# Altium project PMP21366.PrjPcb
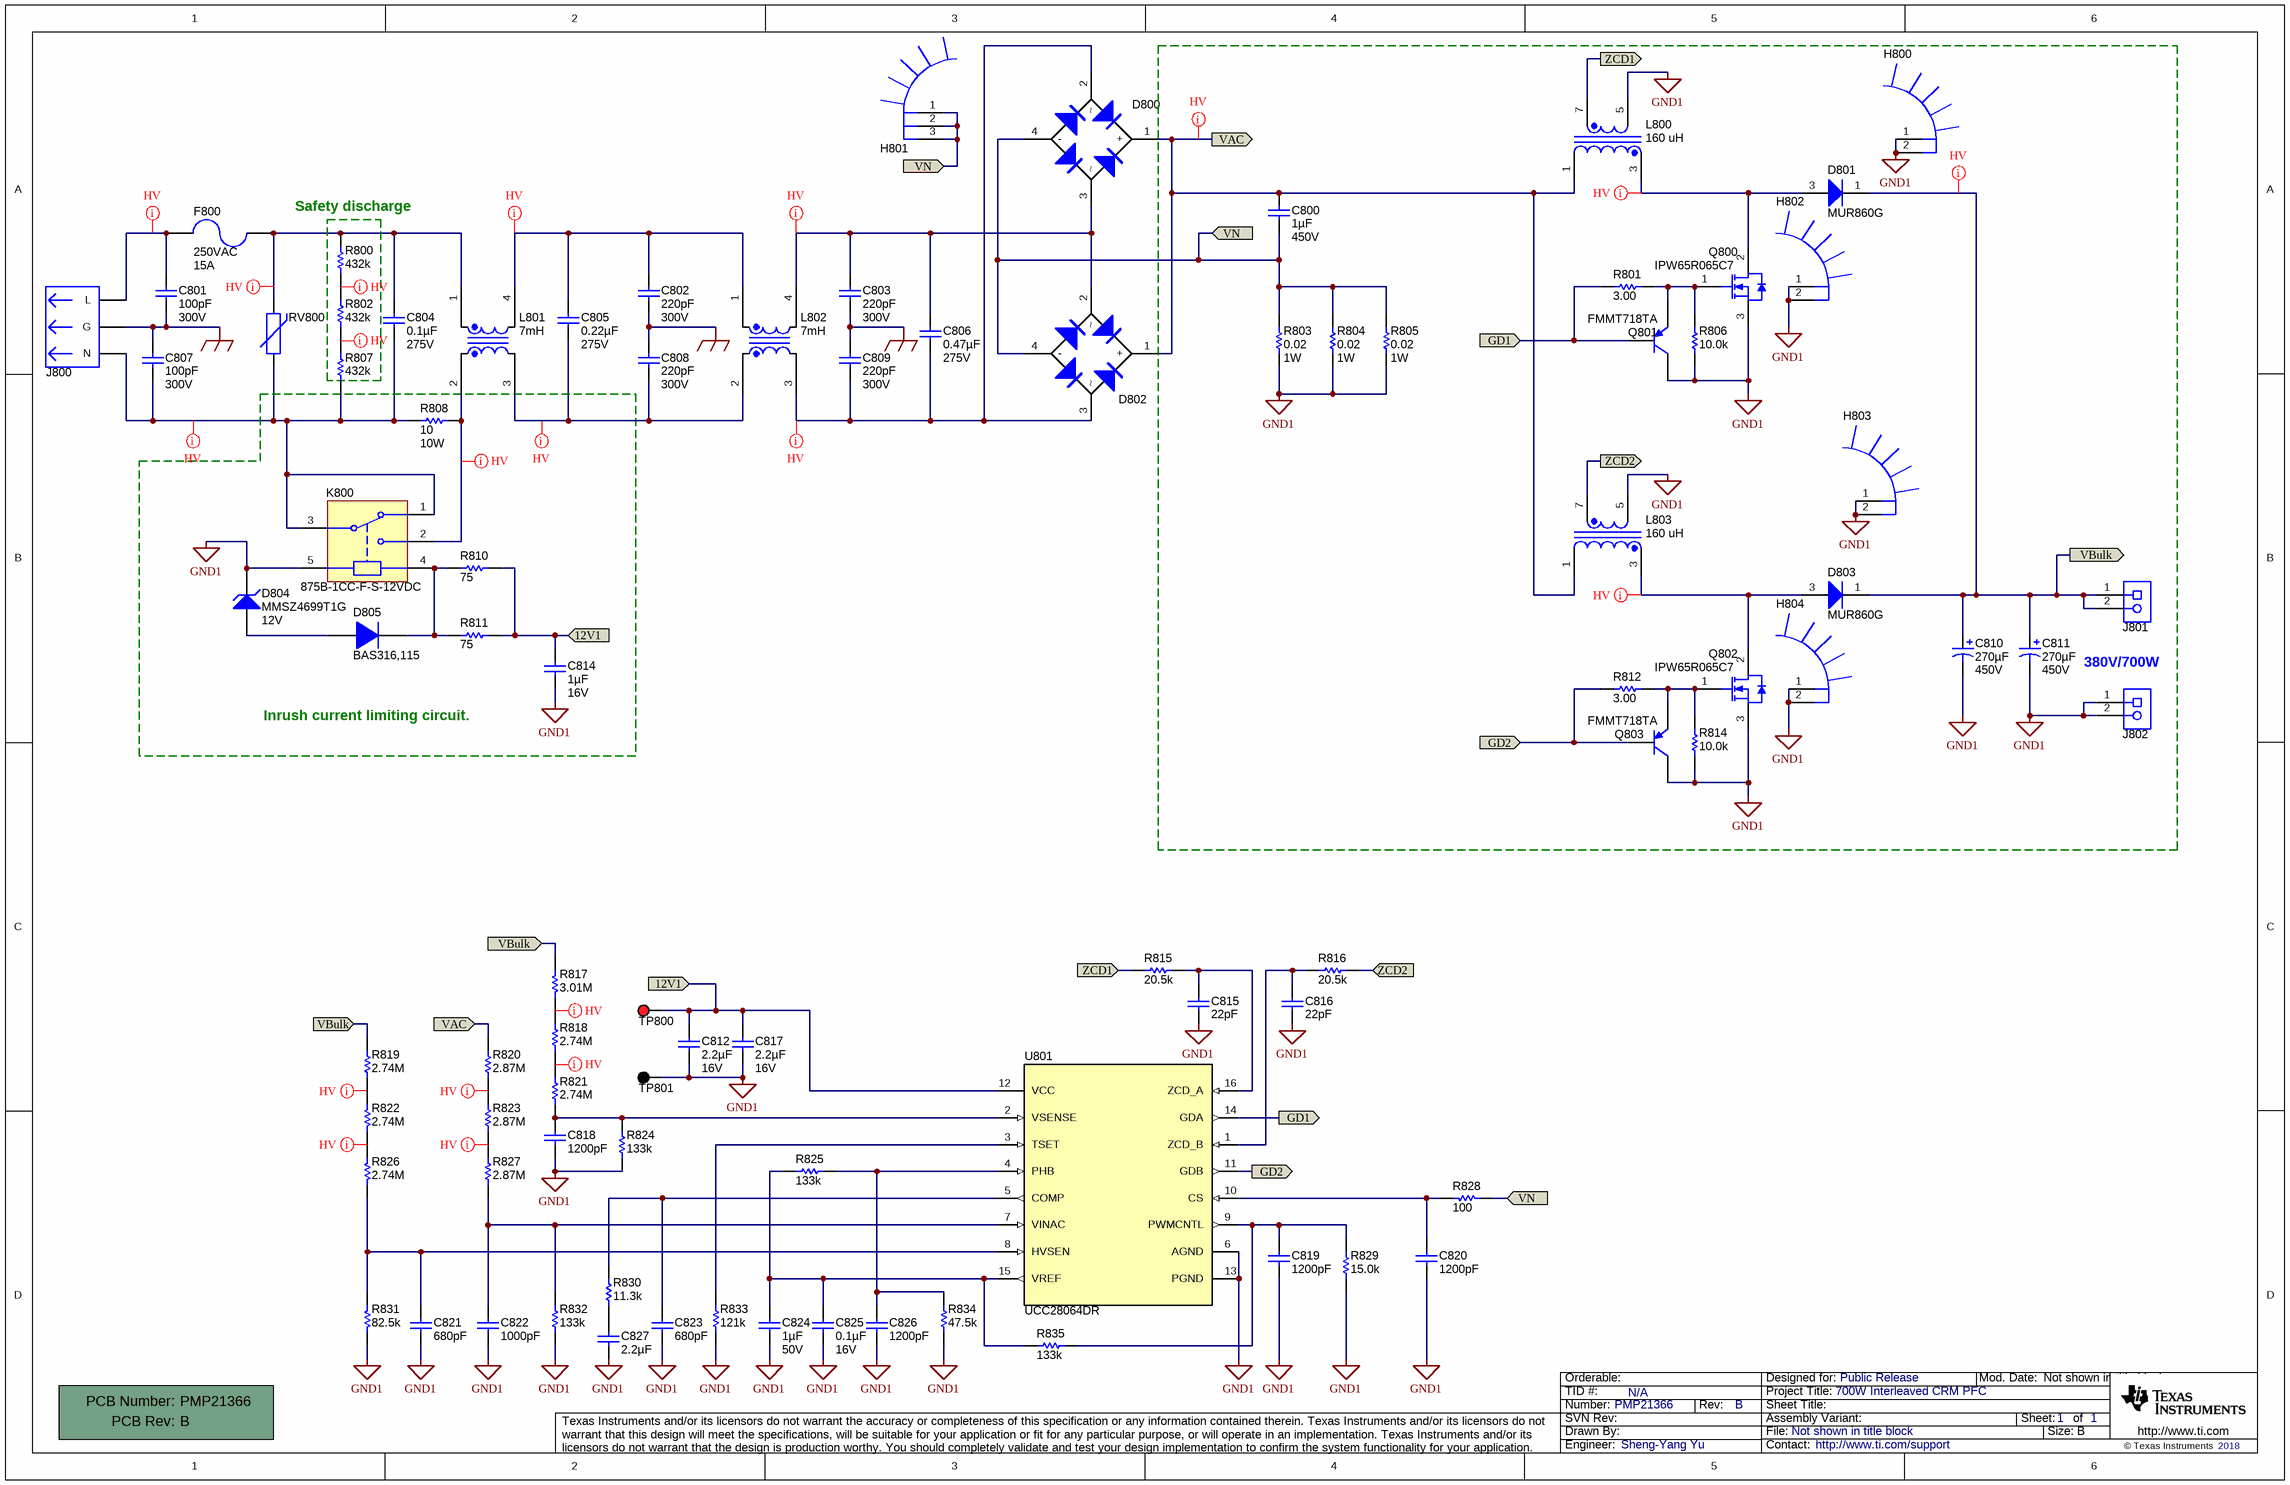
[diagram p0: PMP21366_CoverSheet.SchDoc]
TID: N/A; TechSupport: http://www.ti.com/support; SCH_Rev: B; PRJ_Title: 700W Interleaved CRM PFC; PRJ_Number: PMP21366; PRJ_Engineer: Sheng-Yang Yu; PRJ_Customer: Public Release; PCB_Rev: B; PCB_Layout: Sheng-Yang Yu; CopyrightYear: 2018
1 sheet, 90 parts. Net scope: flat (ports and power ports of the same name join across sheets).
Board file: PMP21366_PCB.PcbDoc

## Sheet PMP21366_CoverSheet.SchDoc
size 431 x 279 mm; Date: Not shown in title block; ApprovedBy: Not shown in title block; CheckedBy: Not shown in title block; Author: Not shown in title block; CompanyName: Not shown in title block; Engineer: Not shown in title block; Organization: Not shown in title block; Address1: Not shown in title block; Address2: Not shown in title block; Address3: Not shown in title block; Address4: Not shown in title block; DocumentNumber: 1; Revision: Use project parameter SCH_Rev; SheetNumber: 1; SheetTotal: 1; PageSetup: Record=PageOptions¦CenterHorizontal=True¦CenterVertical=True¦PrintScale=1.00¦XCorrection=1.00¦YCorrection=1.00¦PrintKind=0¦BorderSize=5000000¦LeftOffset=0¦BottomOffset=0¦Orientation=2¦PaperLength=1000¦PaperWidth=1000¦Scale=100¦PaperSource=15¦PrintQuality=600¦MediaType=1¦DitherType=10¦PaperKind=Letter¦PrintScaleMode=1

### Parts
!PCB800  Printed Circuit Board  (value not drawn)  (mechanical)
C800  ValueDisplayed: 1µF  Value2: 450V  [MPK_1800x950]  (hidden comment: 450MPK105J)
C801  ValueDisplayed: 100pF  VAC_Y: 300V  [KY_700x500x1000]  (hidden comment: DE2B3KY101KN3AU02F)
C802  ValueDisplayed: 220pF  Value2: 300V  [VY2_750x500]  (hidden comment: DE2B3KY221KA3BU02F)
C803  ValueDisplayed: 220pF  Value2: 300V  [VY2_750x500]  (hidden comment: DE2B3KY221KA3BU02F)
C804  ValueDisplayed: 0.1µF  VAC_X: 275V  [WCAP-FTX2_1800x600x1200]  (hidden comment: 890324025017)
C805  ValueDisplayed: 0.22µF  Value2: 275V  [CAPRR1500W60L1750T800H1650]  (hidden comment: ECQ-U2A224ML)
C806  ValueDisplayed: 0.47µF  VAC_X: 275V  [WCAP-FTX2_1500x1000x1600]  (hidden comment: 890324024005)
C807  ValueDisplayed: 100pF  VAC_Y: 300V  [KY_700x500x1000]  (hidden comment: DE2B3KY101KN3AU02F)
C808  ValueDisplayed: 220pF  Value2: 300V  [VY2_750x500]  (hidden comment: DE2B3KY221KA3BU02F)
C809  ValueDisplayed: 220pF  Value2: 300V  [VY2_750x500]  (hidden comment: DE2B3KY221KA3BU02F)
C810  ValueDisplayed: 270µF  Value2: 450V  [380LQ_3000x3000]  (hidden comment: 450VXH270MEFCSN30X30)
C811  ValueDisplayed: 270µF  Value2: 450V  [380LQ_3000x3000]  (hidden comment: 450VXH270MEFCSN30X30)
C812  ValueDisplayed: 2.2µF  Value2: 16V  [0805_HV]  (hidden comment: 0805YD225KAT2A)
C814  ValueDisplayed: 1µF  Value2: 16V  [0805_HV]  (hidden comment: 0805YD105KAT2A)
C815  ValueDisplayed: 22pF  [0603]  (hidden comment: C0603C220J5GACTU)
C816  ValueDisplayed: 22pF  [0603]  (hidden comment: C0603C220J5GACTU)
C817  ValueDisplayed: 2.2µF  Value2: 16V  [0805_HV]  (hidden comment: 0805YD225KAT2A)
C818  ValueDisplayed: 1200pF  [0603]  (hidden comment: 06031C122JAT2A)
C819  ValueDisplayed: 1200pF  [0603]  (hidden comment: 06031C122JAT2A)
C820  ValueDisplayed: 1200pF  [0603]  (hidden comment: 06031C122JAT2A)
C821  ValueDisplayed: 680pF  [0603]  (hidden comment: GRM188R71H681KA01D)
C822  ValueDisplayed: 1000pF  [0603]  (hidden comment: 06031C102MAT2A)
C823  ValueDisplayed: 680pF  [0603]  (hidden comment: GRM188R71H681KA01D)
C824  ValueDisplayed: 1µF  Value2: 50V  [0603]  (hidden comment: UMK107AB7105KA-T)
C825  ValueDisplayed: 0.1µF  Value2: 16V  [0603]  (hidden comment: EMK107B7104KA-T)
C826  ValueDisplayed: 1200pF  [0603]  (hidden comment: 06031C122JAT2A)
C827  ValueDisplayed: 2.2µF  [0805_HV]  (hidden comment: 0805YD225KAT2A)
D800  D25XB60-7000  [5S]  (value not drawn)
D801  MUR860G  [TO-220AC]
D802  D25XB60-7000  [5S]  (value not drawn)
D803  MUR860G  [TO-220AC]
D804  MMSZ4699T1G  value 12V  [SOD-123]
D805  BAS316,115  [sod-323]
F800  VDC_V: 250VAC  Irating_A: 15A  [Fuse_217_015]  (hidden comment: 0217015.MXEP)
H800  513002B02500G  [HSINK_513201B02500]  (value not drawn)
H801  782653B04250G  [HEATSINK_782653B04250G]  (value not drawn)
H802  513002B02500G  [HSINK_513201B02500]  (value not drawn)
H803  513002B02500G  [HSINK_513201B02500]  (value not drawn)
H804  513002B02500G  [HSINK_513201B02500]  (value not drawn)
J800  703W-00/54  [CONN_QUALTEK-703W-0054]  (value not drawn)
J801  1715721  [PhoenixContact_1715721]  (value not drawn)
J802  1715721  [PhoenixContact_1715721]  (value not drawn)
K800  875B-1CC-F-S-12VDC  [RELAY_875]
L800  value 160 uH  [TDK_PFC4124QM-161K06D-00]  (hidden comment: PFC4124QM-161K06D-00)
L801  ValueDisplayed: 7mH  [WE-CMBNC_L]  (hidden comment: 7448040707)
L802  ValueDisplayed: 7mH  [WE-CMBNC_L]  (hidden comment: 7448040707)
L803  value 160 uH  [TDK_PFC4124QM-161K06D-00]  (hidden comment: PFC4124QM-161K06D-00)
Q800  IPW65R065C7  [TO-247]
Q801  FMMT718TA  [SOT-23]
Q802  IPW65R065C7  [TO-247]
Q803  FMMT718TA  [SOT-23]
R800  ValueDisplayed: 432k  [1206]  (hidden comment: CRCW1206432KFKEA)
R801  ValueDisplayed: 3.00  [1206]  (hidden comment: RC1206FR-073RL)
R802  ValueDisplayed: 432k  [1206]  (hidden comment: CRCW1206432KFKEA)
R803  ValueDisplayed: 0.02  Value2: 1W  [2010]  (hidden comment: CSRN2010FK20L0)
R804  ValueDisplayed: 0.02  Value2: 1W  [2010]  (hidden comment: CSRN2010FK20L0)
R805  ValueDisplayed: 0.02  Value2: 1W  [2010]  (hidden comment: CSRN2010FK20L0)
R806  ValueDisplayed: 10.0k  [0805_HV]  (hidden comment: CRCW080510K0FKEA)
R807  ValueDisplayed: 432k  [1206]  (hidden comment: CRCW1206432KFKEA)
R808  ValueDisplayed: 10  Value2: 10W  [TWW10]  (hidden comment: TWW10J10RE)
R810  ValueDisplayed: 75  [1206]  (hidden comment: CRCW120675R0JNEA)
R811  ValueDisplayed: 75  [1206]  (hidden comment: CRCW120675R0JNEA)
R812  ValueDisplayed: 3.00  [1206]  (hidden comment: RC1206FR-073RL)
R814  ValueDisplayed: 10.0k  [0805_HV]  (hidden comment: CRCW080510K0FKEA)
R815  ValueDisplayed: 20.5k  [0603]  (hidden comment: CRCW060320K5FKEA)
R816  ValueDisplayed: 20.5k  [0603]  (hidden comment: CRCW060320K5FKEA)
R817  ValueDisplayed: 3.01M  [0805_HV]  (hidden comment: CRCW08053M01FKEA)
R818  ValueDisplayed: 2.74M  [0805_HV]  (hidden comment: CRCW08052M74FKEA)
R819  ValueDisplayed: 2.74M  [0805_HV]  (hidden comment: CRCW08052M74FKEA)
R820  ValueDisplayed: 2.87M  [0805_HV]  (hidden comment: CRCW08052M87FKEA)
R821  ValueDisplayed: 2.74M  [0805_HV]  (hidden comment: CRCW08052M74FKEA)
R822  ValueDisplayed: 2.74M  [0805_HV]  (hidden comment: CRCW08052M74FKEA)
R823  ValueDisplayed: 2.87M  [0805_HV]  (hidden comment: CRCW08052M87FKEA)
R824  ValueDisplayed: 133k  [0603]  (hidden comment: CRCW0603133KFKEA)
R825  ValueDisplayed: 133k  [0603]  (hidden comment: CRCW0603133KFKEA)
R826  ValueDisplayed: 2.74M  [0805_HV]  (hidden comment: CRCW08052M74FKEA)
R827  ValueDisplayed: 2.87M  [0805_HV]  (hidden comment: CRCW08052M87FKEA)
R828  ValueDisplayed: 100  [0603]  (hidden comment: CRCW0603100RFKEA)
R829  ValueDisplayed: 15.0k  [0603]  (hidden comment: CRCW060315K0FKEA)
R830  ValueDisplayed: 11.3k  [0603]  (hidden comment: CRCW060311K3FKEA)
R831  ValueDisplayed: 82.5k  [0603]  (hidden comment: CRCW060382K5FKEA)
R832  ValueDisplayed: 133k  [0603]  (hidden comment: CRCW0603133KFKEA)
R833  ValueDisplayed: 121k  [0603]  (hidden comment: CRCW0603121KFKEA)
R834  ValueDisplayed: 47.5k  [0603]  (hidden comment: RC0603FR-0747K5L)
R835  ValueDisplayed: 133k  [0603]  (hidden comment: CRCW0603133KFKEA)
RV800  S10K275E2  [VAR_S10K275E2]  (value not drawn)
TP800  5000  [Keystone5000]  (value not drawn)
TP801  5001  [Keystone5001]  (value not drawn)
U801  UCC28064DR  [D0016A_N]

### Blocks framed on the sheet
380V/700W: C800 C810 C811 D801 D803 H800 H802-H804 J801 J802 L800 L803 Q800-Q803 R801 R803-R806 R812 R814
Safety discharge: R800 R802 R807
Inrush current limiting circuit.: C814 D804 D805 K800 R808 R810 R811

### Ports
12V1 (in), GD1 (in), GD1 (out), GD2 (in), GD2 (out), VAC (in), VAC (out), VBulk (in), VBulk (out), VN (in), ZCD1 (in), ZCD1 (out), ZCD2 (in), ZCD2 (out)

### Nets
GND1: C810.2(-) C811.2(-) C812.2 C814.1 C815.2 C816.2 C817.2 C818.2 C819.2 C820.2 C821.2 C822.2 C823.2 C824.2 C825.2 C826.2 C827.2 D804.1(K) H800.1 H800.2 H802.1 H802.2 H803.1 H803.2 H804.1 H804.2 J802.1 J802.2 K800.5 L800.5 L803.5 Q800.3(S) Q801.3(C) Q802.3(S) Q803.3(C) R803.2 R804.2 R805.2 R806.1 R814.1 R824.1 R829.1 R831.1 R832.1 R833.1 R834.1 TP801.1 U801.6(AGND) U801.13(PGND)
PE: C801.1 C802.1 C803.1 C807.2 C808.2 C809.2 J800.3(G)
12V1: C812.1 C814.2 C817.1 R810.2 R811.2 TP800.1 U801.12(VCC) ; port 12V1
GD1: Q801.1(B) R801.1 U801.14(GDA) ; port GD1
GD2: Q803.1(B) R812.1 U801.11(GDB) ; port GD2
VAC: C800.1 D800.1(+) D802.1(+) L800.1 L803.1 R820.2 ; port VAC
VBulk: C810.1(+) C811.1(+) D801.1(K) D803.1(K) J801.1 J801.2 R817.2 R819.2 ; port VBulk
VN: C800.2 D800.4(-) D802.4(-) H801.1 H801.2 H801.3 R803.1 R804.1 R805.1 R828.1 ; port VN
ZCD1: L800.7 R815.1 ; port ZCD1
ZCD2: L803.7 R816.2 ; port ZCD2
NetC801_2: C801.2 F800.2 J800.1(L)
NetC802_2: C802.2 C805.1 L801.4 L802.1
NetC803_2: C803.2 C806.1 D800.3 D802.2 L802.4
NetC804_1: C804.1 F800.1 L801.1 R800.2 RV800.2
NetC804_2: C804.2 C807.1 J800.2(N) K800.1 K800.3 R807.1 R808.2 RV800.1
NetC805_2: C805.2 C808.1 L801.3 L802.2
NetC806_2: C806.2 C809.1 D800.2 D802.3 L802.3
NetC815_1: C815.1 R815.2 U801.16(ZCD_A)
NetC816_1: C816.1 R816.1 U801.1(ZCD_B)
NetC818_1: C818.1 R821.1 R824.2 U801.2(VSENSE)
NetC819_1: C819.1 R829.2 R835.2 U801.9(PWMCNTL)
NetC820_1: C820.1 R828.2 U801.10(CS)
NetC821_1: C821.1 R826.1 R831.2 U801.8(HVSEN)
NetC822_1: C822.1 R827.1 R832.2 U801.7(VINAC)
NetC823_1: C823.1 R830.2 U801.5(COMP)
NetC824_1: C824.1 C825.1 R825.1 R835.1 U801.15(VREF)
NetC826_1: C826.1 R825.2 R834.2 U801.4(PHB)
NetC827_1: C827.1 R830.1
NetD801_3: D801.3(A) L800.3 Q800.2(D)
NetD803_3: D803.3(A) L803.3 Q802.2(D)
NetD804_2: D804.2(A) D805.2(A)
NetD805_1: D805.1(K) K800.4 R810.1 R811.1
NetK800_2: K800.2 L801.2 R808.1
NetQ800_1: Q800.1(G) Q801.2(E) R801.2 R806.2
NetQ802_1: Q802.1(G) Q803.2(E) R812.2 R814.2
NetR800_1: R800.1 R802.2
NetR802_1: R802.1 R807.2
NetR817_1: R817.1 R818.2
NetR818_1: R818.1 R821.2
NetR819_1: R819.1 R822.2
NetR820_1: R820.1 R823.2
NetR822_1: R822.1 R826.2
NetR823_1: R823.1 R827.2
NetR833_2: R833.2 U801.3(TSET)

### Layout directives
net class HV: NetC801_2, NetC802_2, NetC803_2, NetC804_1, NetC804_2, NetC805_2, NetC806_2, NetD801_3, NetD803_3, NetK800_2, NetR800_1, NetR802_1, NetR817_1, NetR818_1, NetR819_1, NetR820_1, NetR822_1, NetR823_1, VAC, VBulk

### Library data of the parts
!PCB800 = PCB: Manufacturer: Any; PartNumber: PMP21366; SymbolCreator: a0412235
C800 = 450MPK105J: CAP, Film, 1 µF, 450 V,+/- 5%, TH; Manufacturer: Rubycon; Polarized: N; CompType: Capacitor; Value: 1uF; U/M: EA; Cap_F: 0.000001; Tolerance_%: 5; VDC_V: 450; TaMin_C: -40; TaMax_C: 105; Cap_Case: 18x9.5mm; AEC Category: Q200
C801 C807 = DE2B3KY101KN3AU02F: CAP, CERM, 100 pF, X1 250 VAC/Y2 300 VAC, +/- 10%, B, TH, 2- Leads, Body 7x5mm, Pin Spacing 7.5mm; Manufacturer: MuRata; Polarized: N; CompType: Capacitor; Value: 100pF; U/M: EA; Cap_F: 0.0000000001; Tolerance_%: 10; TaMin_C: -25; TaMax_C: 85; Cap_Case: 7x5x10mm; SizeArea_mm2: 37.5; SizeAreaWB_mm2: 66.5; SizeX_mm: 7.5; SizeY_mm: 5; AEC Category: Q200; AC_Safety: X1Y2; VAC_X: 250
C802 C803 C808 C809 = VY2471K29Y5SS63V7: CAP CER 220PF 300VAC 10% RADIAL; Manufacturer: Murata; Polarized: N; CompType: Capacitor; U/M: EA; Cap_F: 0.00000000047; Tolerance_%: 10; Value1: Unknown; TempCo: VY2; TaMin_C: -40; TaMax_C: 125; Cap_Case: Disk, 5x7.5 mm
C804 = 890324025017: CAP, Film, 0.1 µF, X2 275 VAC, +/- 10%, TH; Manufacturer: Wurth Elektronik; Polarized: N; CompType: Capacitor; Value: 0.1uF; U/M: EA; Cap_F: 0.0000001; Tolerance_%: 10; TaMin_C: -40; TaMax_C: 105; Cap_Case: 18x6x12mm; AEC Category: Q200; Green_Lifecycle: Not Set; Green_REACh: Incomplete
C805 = ECQ-U2A224ML: CAP, Film, 0.22 µF, 275 V,+/- 20%, TH; Manufacturer: Panasonic; Polarized: N; CompType: Capacitor; Value: 0.22uF; U/M: EA; Cap_F: 0.00000022; Tolerance_%: 20; VDC_V: 275; TaMin_C: -40; TaMax_C: 100; Cap_Case: Radial 17.5x8x16.5; SizeAreaWB_mm2: 195; SizeArea_mm2: 140; SizeX_mm: 17.5; SizeY_mm: 8; SizeZ_mm: 16.5; AEC Category: Q200
C806 = 890324024005: CAP, Film, 0.47 µF, X2 275 VAC, +/- 10%, TH; Manufacturer: Wurth Elektronik; Polarized: N; CompType: Capacitor; Value: 0.47uF; U/M: EA; Cap_F: 0.00000047; Tolerance_%: 10; TaMin_C: -40; TaMax_C: 105; Cap_Case: 15x10x16mm; SizeAreaWB_mm2: 204; SizeArea_mm2: 150; SizeX_mm: 15; SizeZ_mm: 16.5; AEC Category: Q200; Green_Lifecycle: Not Set; Green_REACh: Incomplete
C810 C811 = 380LQ271M450K022: CAP ALUM 270UF 450V 20% SNAP; Manufacturer: Rubycon; Polarized: Y; CompType: Capacitor; U/M: EA; Cap_F: 0.00027; Tolerance_%: 20; Value1: 0.737 ohm; VDC_V: 450; ESR_ohm: 0.737; IRMS_A: 1.78; TaMin_C: -25; TaMax_C: 85; Cap_Case: 30x30mm
C812 C817 = 0805YD225KAT2A: CAP, CERM, 2.2 µF, 16 V, +/- 10%, X5R, 0805; Manufacturer: AVX; Polarized: N; CompType: Capacitor; Value: 2.2uF; U/M: EA; Cap_F: 0.0000022; Tolerance_%: 10; ESR_ohm: 0.009; Value1: 0.009 ohm; VDC_V: 16; TaMin_C: -55; TaMax_C: 85; Cap_Case: 0805
C814 = 0805YD105KAT2A: CAP, CERM, 1uF, 16V, +/-10%, X5R, 0805; Manufacturer: AVX; Polarized: N; CompType: Capacitor; U/M: EA; Cap_F: 0.000001; Tolerance_%: 10; ESR_Ohm: 0.012; Value1: 0.012 ohm; VDC_V: 16; TaMin_C: -55; TaMax_C: 85; Cap_Case: 0805
C815 C816 = C0603C220J5GACTU: CAP, CERM, 22 pF, 50 V, +/- 5%, C0G/NP0, 0603; Manufacturer: Kemet; Polarized: N; CompType: Capacitor; Value: 22pF; U/M: EA; Cap_F: 0.000000000022; Tolerance_%: 5; Value1: Unknown; VDC_V: 50; Value2: 50V; TaMin_C: -55; TaMax_C: 125
C818-C820 C826 = 06031C122JAT2A: CAP, CERM, 1200 pF, 100 V,+/- 5%, X7R, 0603; Manufacturer: AVX; Polarized: N; CompType: Capacitor; Value: 1200pF; U/M: EA; Cap_F: 0.0000000012; Tolerance_%: 5; ESR_ohm: 0.254; Value1: 0.254 ohm; VDC_V: 100; Value2: 100V; TaMin_C: -55; TaMax_C: 125; SizeArea_mm2: 1.28; SizeAreaWB_mm2: 4.68; SizeX_mm: 1.6; SizeY_mm: 0.8; SizeZ_mm: 1; AEC Category: Q200; Green_Lifecycle: Not Set; Green_REACh: Incomplete
C821 C823 = GRM188R71H681KA01D: CAP, CERM, 680 pF, 50 V, +/- 10%, X7R, 0603; Manufacturer: MuRata; Polarized: N; CompType: Capacitor; Value: 680pF; U/M: EA; Cap_F: 0.00000000068; Tolerance_%: 10; Value1: Unknown; VDC_V: 50; Value2: 50V; TaMin_C: -55; TaMax_C: 125
C822 = 06031C102MAT2A: CAP, CERM, 1000 pF, 100 V, +/- 20%, X7R, 0603; Manufacturer: AVX; Polarized: N; CompType: Capacitor; Value: 1000pF; U/M: EA; Cap_F: 0.000000001; Tolerance_%: 20; ESR_ohm: 0.276; Value1: 0.276 ohm; VDC_V: 100; Value2: 100V; TaMin_C: -55; TaMax_C: 125
C824 = UMK107AB7105KA-T: CAP, CERM, 1 µF, 50 V, +/- 10%, X7R, 0603; Manufacturer: Taiyo Yuden; Polarized: N; CompType: Capacitor; Value: 1uF; U/M: EA; Cap_F: 0.000001; Tolerance_%: 10; Value1: Unknown; VDC_V: 50; TaMin_C: -55; TaMax_C: 125
C825 = EMK107B7104KA-T: CAP, CERM, 0.1 µF, 16 V, +/- 10%, X7R, 0603; Manufacturer: Taiyo Yuden; Polarized: N; CompType: Capacitor; Value: 0.1uF; U/M: EA; Cap_F: 0.0000001; Tolerance_%: 10; Value1: Unknown; VDC_V: 16; TaMin_C: -55; TaMax_C: 125
C827 = 0805YD225KAT2A: CAP, CERM, 2.2 µF, 16 V, +/- 10%, X5R, 0805; Manufacturer: AVX; Polarized: N; CompType: Capacitor; Value: 2.2uF; U/M: EA; Cap_F: 0.0000022; Tolerance_%: 10; ESR_ohm: 0.009; Value1: 0.009 ohm; VDC_V: 16; Value2: 16V; TaMin_C: -55; TaMax_C: 85; Cap_Case: 0805
D800 D802 = D25XB60-7000: Diode, Switching-Bridge, 600 V, 3.5 A, TH; Manufacturer: Shindengen; U/M: EA; Vf_V: 1.05; Value: 600V; Value1: 3.5A; Value2: 1.05V; Io_A: 3.5; Vr_V: 600; TJmax_C: 150
D801 D803 = MUR860G: Diode, Ultrafast, 600V, 8A, TH; Manufacturer: ON Semiconductor; SymbolCreator: a0412235; Value: 0.98V; U/M: EA; Vf_V: 0.98; Io_A: 8; Vr_V: 600; TJmax_C: 175; RJC_CperW: 4.75
D804 = MMSZ4699T1G: Diode, Zener, 12 V, 500 mW, SOD-123; Manufacturer: ON Semiconductor; SymbolCreator: a0412235; U/M: EA; Power_W: 0.5; Vz_V: 12; Value1: 0.5W; RJA_CperW: 340
D805 = BAS316,115: Diode, Ultrafast, 100 V, 0.25 A, SOD-323; Manufacturer: NXP Semiconductor; U/M: EA; Vf_V: 1.4; Value: 100V; Value1: 0.25A; Value2: 1.4V; Io_A: 0.25; Vr_V: 100; TJmax_C: 150
F800 = 0217015.MXEP: Fuse, 15 A, 250 VDC, TH; Manufacturer: Littelfuse; Rtyp_Ohm: 0.04; MeltingTyp: 617.135
H800 H802-H804 = 513201B02500G: BOARD LEVEL HEATSINK .5" TO-220; Manufacturer: Aavid; SymbolCreator: a0799628
H801 = 782653B04250G: HEATSINK VERT MAX CLIP, BLACK, 4.25 INCHES; Manufacturer: Aavid; SymbolCreator: a0411947; Green_Lifecycle: Not Set; Green_REACh: Incomplete
J800 = 703W-00/54: AC Receptacle, 10A 250VAC; Manufacturer: Qualtek Electronics Corporation; SymbolCreator: a0799628; CompType: Connector; U/M: EA
J801 J802 = 1715721: Conn Term Block, 2POS, 5.08mm, TH; Manufacturer: Phoenix Contact; SymbolCreator: a0412235; CompType: Terminal Block; U/M: EA; Value: 2x1
K800 = 875B-1CC-F-S-12VDC: Relay, SPDT ( 1 Form C), 16A, 12 VDC, TH; Manufacturer: SONG CHUAN; SymbolCreator: Altium; Coil Current: 30 mA; Coil Power: 360 mW; Coil Resistance: 400 ohms; Coil Voltage: 12 VDC; Turn Off Voltage (Min): 0.6 VDC; Turn On Voltage (Max): 9 VDC; Time Operate (s): 0.015; Time Release (s): 0.01
L800 L803 = PFC4124QM-161K06D-00: Transformer, 160 uH, TH; Manufacturer: TDK; SymbolCreator: Altium; U/M: EA
L801 L802 = 7448040707: Coupled inductor, 7 mH, 7 A, 0.02 ohm, TH; Manufacturer: Wurth Elektronik; SymbolCreator: a0799628; Value: 7mH; Ind_H: 7.0E-3; DCR_ohm: 0.02; AEC Category: Q200
Q800 Q802 = IPW60R125CP: MOSFET N-CH 600V 53A TO247; Manufacturer: Infineon Technologies; Alternate Manufacturer: None; U/M: EA; ChType: N; Value: 650V; Value1: ? ohm; QgTyp_nC: 53; Vgs_V: 20; IdsMax_A: 25
Q801 Q803 = FMMT718TA, Diodes Inc.: Transistor, PNP, 20V, 1.5A, SOT-23; CompType: BJT; PNP: 1; NPN: 0; Vceo_V: 20; IcRated_A: 1.5; HfeMax: 6; U/M: EA
R800 R802 R807 = CRCW1206432KFKEA: RES, 432 k, 1%, 0.25 W, 1206; Manufacturer: Vishay-Dale; CompType: Resistor; Value: 432k; Res_ohm: 432000; Tolerance_%: 1; Power_W: 0.25; Value2: 0.25W; VDC_V: 200; TempCo: 100 ppm/C; EIA_Code: E96; U/M: EA
R801 R812 = RC1206FR-073RL: RES, 3.00, 1%, 0.25 W, 1206; Manufacturer: Yageo America; CompType: Resistor; Value: 3.00; Res_ohm: 3; Value_Code: 3R00; Tolerance_%: 1; Power_W: 0.25; Value2: 0.25W; VDC_V: 200; TempCo: 200 ppm/C; SizeArea_mm2: 5.12; SizeX_mm: 3.2; SizeY_mm: 1.6; SizeZ_mm: 1.35; U/M: EA; AEC Category: Q200; Green_Lifecycle: Active; Green_REACh: Passed
R803-R805 = CSRN2010FK20L0: RES, 0.02, 1%, 1 W, 2010; Manufacturer: Stackpole Electronics Inc; CompType: Resistor; Value: 0.02; Value_Code: R020; Tolerance_%: 1; TempCo: 250 ppm/C; EIA_Code: E96; U/M: EA
R806 R814 = CRCW080510K0FKEA: RES, 10.0 k, 1%, 0.125 W, 0805; Manufacturer: Vishay-Dale; CompType: Resistor; Value: 10.0k; Res_ohm: 10000; Value_Code: 10k0; Tolerance_%: 1; Power_W: 0.125; Value2: 0.125W; VDC_V: 150; TempCo: 100 ppm/C; EIA_Code: E96; U/M: EA
R808 = TWW10J10RE: RES, 10, 5%, 10 W, TH; Manufacturer: Ohmite; CompType: Resistor; Value: 10; Value_Code: 10R0; Tolerance_%: 5; VDC_V: 750; TempCo: 400 ppm/C; EIA_Code: E24; U/M: EA
R810 R811 = CRCW120675R0JNEA: RES, 75, 5%, 0.25 W, 1206; Manufacturer: Vishay-Dale; CompType: Resistor; Value: 75; Value_Code: 75R0; Tolerance_%: 5; Power_W: 0.25; Value2: 0.25W; VDC_V: 200; TempCo: 200 ppm/C; EIA_Code: E24; U/M: EA
R815 R816 = CRCW060320K5FKEA: RES, 20.5 k, 1%, 0.1 W, 0603; Manufacturer: Vishay-Dale; CompType: Resistor; Value: 20.5k; Res_ohm: 20500; Value_Code: 20k5; Tolerance_%: 1; Power_W: 0.1; Value2: 0.1W; VDC_V: 75; TempCo: 100 ppm/C; EIA_Code: E96; U/M: EA
R817 = CRCW08053M01FKEA: RES, 3.01 M, 1%, 0.125 W, 0805; Manufacturer: Vishay-Dale; CompType: Resistor; Value: 3.01Meg; Res_ohm: 3010000; Value_Code: 3M01; Tolerance_%: 1; Power_W: 0.125; Value2: 0.125W; VDC_V: 150; TempCo: 100 ppm/C; EIA_Code: E96; U/M: EA
R818 R819 R821 R822 R826 = CRCW08052M74FKEA: RES, 2.74 M, 1%, 0.125 W, 0805; Manufacturer: Vishay-Dale; CompType: Resistor; Value: 2.74Meg; Res_ohm: 2740000; Value_Code: 2M74; Tolerance_%: 1; Power_W: 0.125; Value2: 0.125W; VDC_V: 150; TempCo: 100 ppm/C; EIA_Code: E96; U/M: EA
R820 R823 R827 = CRCW08052M87FKEA: RES, 2.87 M, 1%, 0.125 W, 0805; Manufacturer: Vishay-Dale; CompType: Resistor; Value: 2.87Meg; Res_ohm: 2870000; Value_Code: 2M87; Tolerance_%: 1; Power_W: 0.125; Value2: 0.125W; VDC_V: 150; TempCo: 100 ppm/C; EIA_Code: E96; U/M: EA
R824 R832 = CRCW0603133KFKEA: RES, 133 k, 1%, 0.1 W, 0603; Manufacturer: Vishay-Dale; CompType: Resistor; Value: 133k; Res_ohm: 133000; Tolerance_%: 1; Power_W: 0.1; Value2: 0.1W; VDC_V: 75; TempCo: 100 ppm/C; EIA_Code: E96; U/M: EA
R825 R835 = CRCW0603133KFKEA: RES, 133 k, 1%, 0.1 W, 0603; Manufacturer: Vishay-Dale; CompType: Resistor; Value: 133k; Res_ohm: 133000; Tolerance_%: 1; Power_W: 0.1; Value2: 0.1W; VDC_V: 75; TempCo: 100 ppm/C; SizeArea_mm2: 1.28; SizeX_mm: 1.6; SizeY_mm: 0.8; EIA_Code: E96; U/M: EA; AEC Category: Q200; Green_Lifecycle: Active; Green_REACh: Passed
R828 = CRCW0603100RFKEA: RES, 100, 1%, 0.1 W, 0603; Manufacturer: Vishay-Dale; CompType: Resistor; Value: 100; Value_Code: 100R; Tolerance_%: 1; Power_W: 0.1; Value2: 0.1W; VDC_V: 75; TempCo: 100 ppm/C; EIA_Code: E96; U/M: EA
R829 = CRCW060315K0FKEA: RES, 15.0 k, 1%, 0.1 W, 0603; Manufacturer: Vishay-Dale; CompType: Resistor; Value: 15.0k; Res_ohm: 15000; Value_Code: 15k0; Tolerance_%: 1; Power_W: 0.1; Value2: 0.1W; VDC_V: 75; TempCo: 100 ppm/C; SizeArea_mm2: 1.28; SizeX_mm: 1.6; SizeY_mm: 0.8; EIA_Code: E96; U/M: EA; AEC Category: Q200; Green_Lifecycle: Active; Green_REACh: Passed
R830 = CRCW060311K3FKEA: RES, 11.3 k, 1%, 0.1 W, 0603; Manufacturer: Vishay-Dale; CompType: Resistor; Value: 11.3k; Res_ohm: 11300; Value_Code: 11k3; Tolerance_%: 1; Power_W: 0.1; Value2: 0.1W; VDC_V: 75; TempCo: 100 ppm/C; EIA_Code: E96; U/M: EA
R831 = CRCW060382K5FKEA: RES, 82.5 k, 1%, 0.1 W, 0603; Manufacturer: Vishay-Dale; CompType: Resistor; Value: 82.5k; Res_ohm: 82500; Value_Code: 82k5; Tolerance_%: 1; Power_W: 0.1; Value2: 0.1W; VDC_V: 75; TempCo: 100 ppm/C; EIA_Code: E96; U/M: EA
R833 = CRCW0603121KFKEA: RES, 121 k, 1%, 0.1 W, 0603; Manufacturer: Vishay-Dale; CompType: Resistor; Value: 121k; Res_ohm: 121000; Tolerance_%: 1; Power_W: 0.1; Value2: 0.1W; VDC_V: 75; TempCo: 100 ppm/C; EIA_Code: E96; U/M: EA
R834 = RC0603FR-0747K5L: RES, 47.5 k, 1%, 0.1 W, 0603; Manufacturer: Yageo America; CompType: Resistor; Value: 47.5k; Res_ohm: 47500; Value_Code: 47k5; Tolerance_%: 1; Power_W: 0.1; Value2: 0.1W; VDC_V: 150; TempCo: 200 ppm/C; SizeArea_mm2: 1.28; SizeX_mm: 1.6; SizeY_mm: 0.8; EIA_Code: E96; U/M: EA; AEC Category: Q200; Green_Lifecycle: Active; Green_REACh: Passed
RV800 = S10K275E2: Varistor 275V RMS 10MM Radial, TH; Manufacturer: EPCOS Inc; SymbolCreator: a0412235
TP800 = 5000: Test Point, Miniature, Red, TH; Manufacturer: Keystone; CompType: Test Point Loop; ContactFinish: Silver; Green_Lifecycle: Active; Green_REACh: Passed
TP801 = 5001: Test Point, Miniature, Black, TH; Manufacturer: Keystone; CompType: Test Point Loop; ContactFinish: Silver; Green_Lifecycle: Active; Green_REACh: Passed
U801 = UCC28064DR: Natural Interleaving Transition Mode PFC Controller with Improved Light Load Efficiency, D0016A (SOIC-16); Manufacturer: Texas Instruments; SymbolCreator: Altium; SizeArea_mm2: 59.4; SizeAreaWB_mm2: 95.2; SizeX_mm: 6; SizeY_mm: 9.9; SizeZ_mm: 1.75; CompType: IC; U/M: EA

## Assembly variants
001: not fitted FID1 FID2 FID3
